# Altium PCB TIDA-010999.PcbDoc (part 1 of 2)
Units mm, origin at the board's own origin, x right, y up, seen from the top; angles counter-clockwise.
Board outline 95 x 90.17 mm, 4 copper layers (Top Layer 1, Top Layer, Bottom Layer, Bottom Layer 1), stack 1.926 mm thick; 90 components, 100 nets, 358 pads, 545 vias.
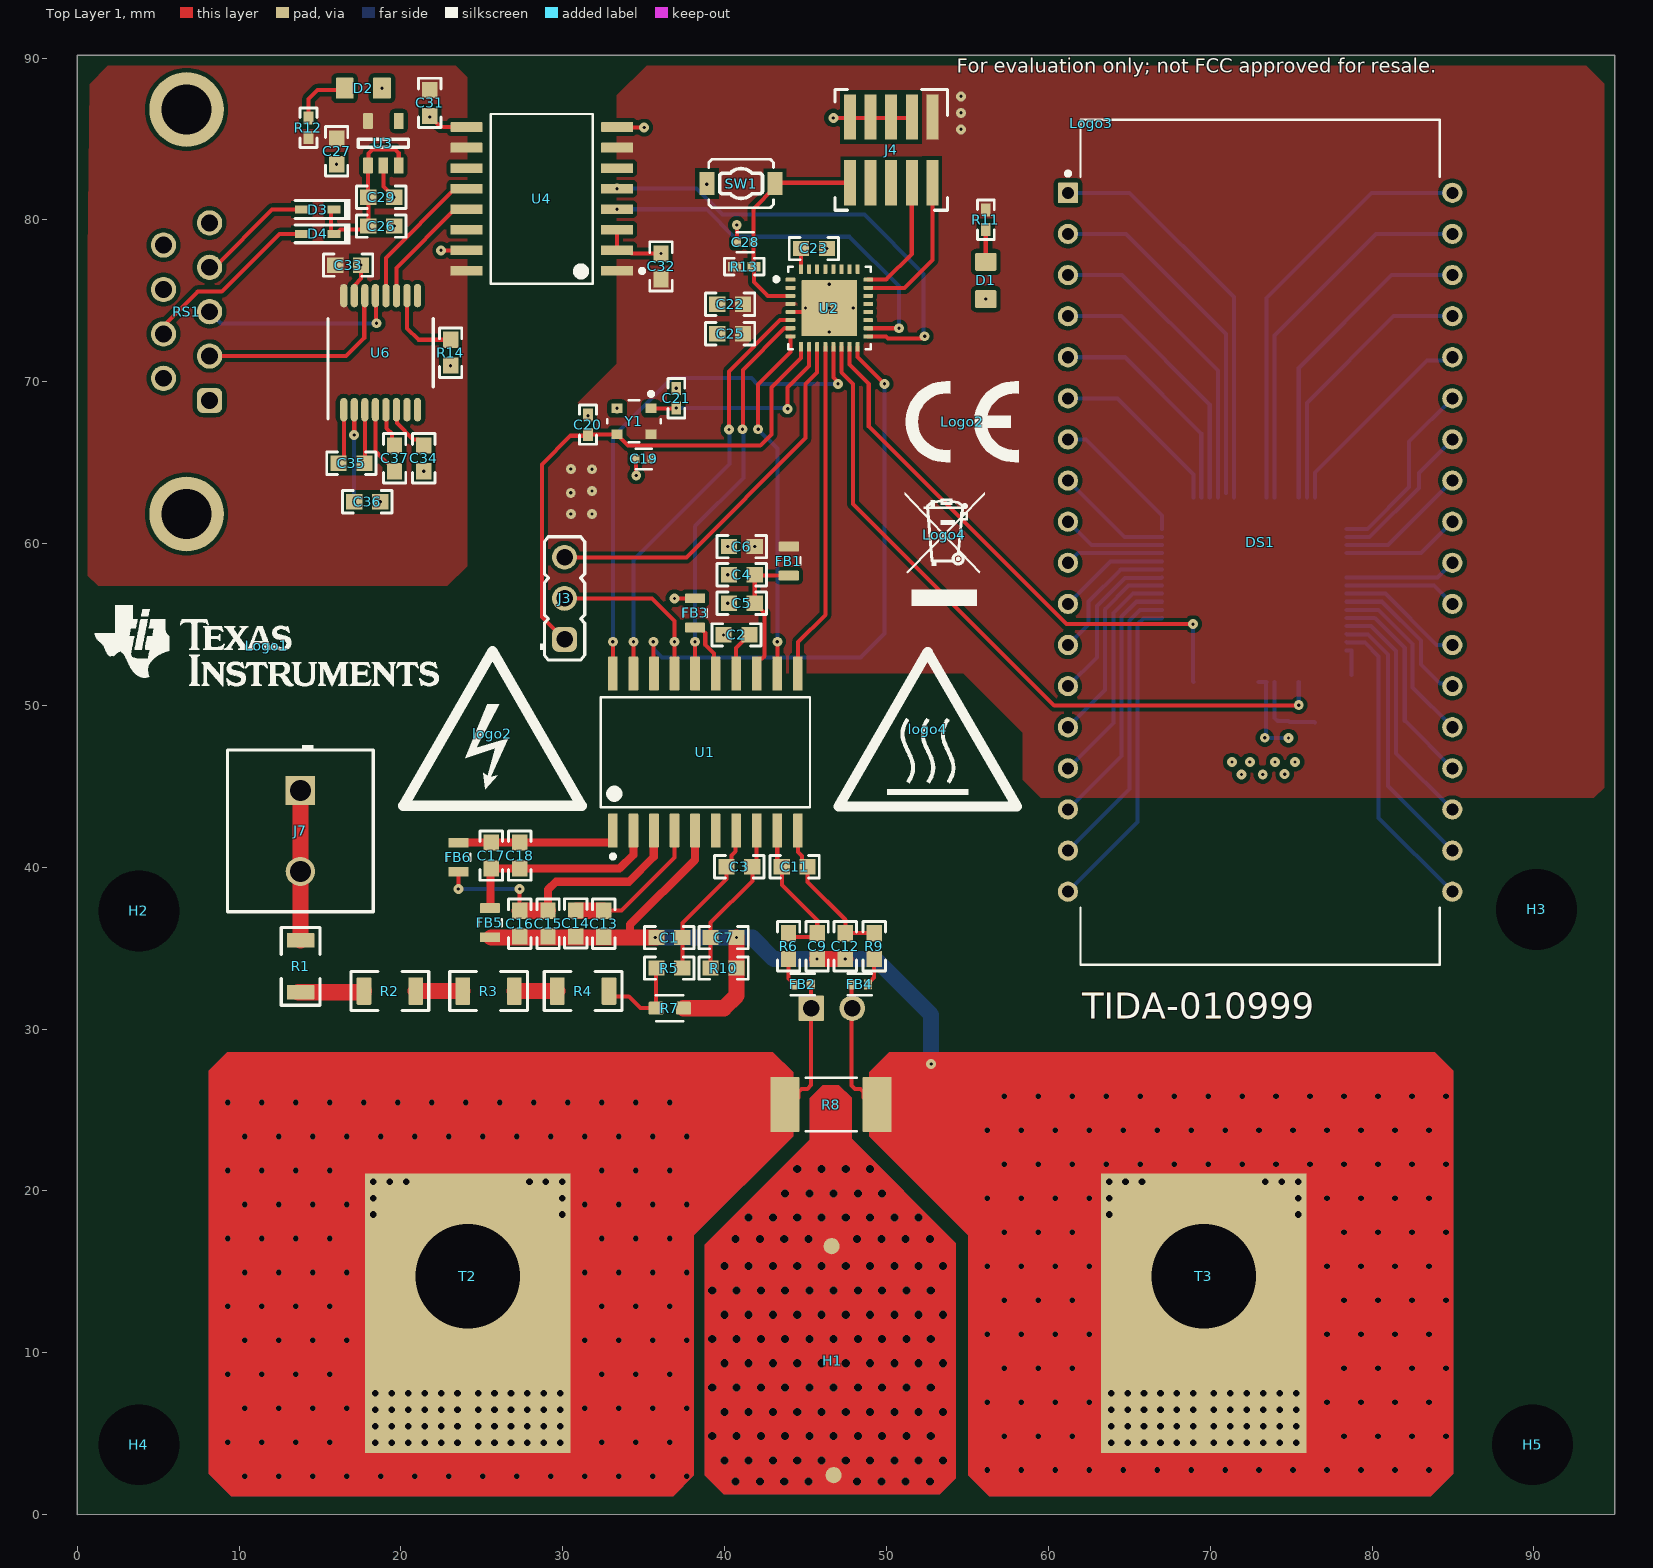
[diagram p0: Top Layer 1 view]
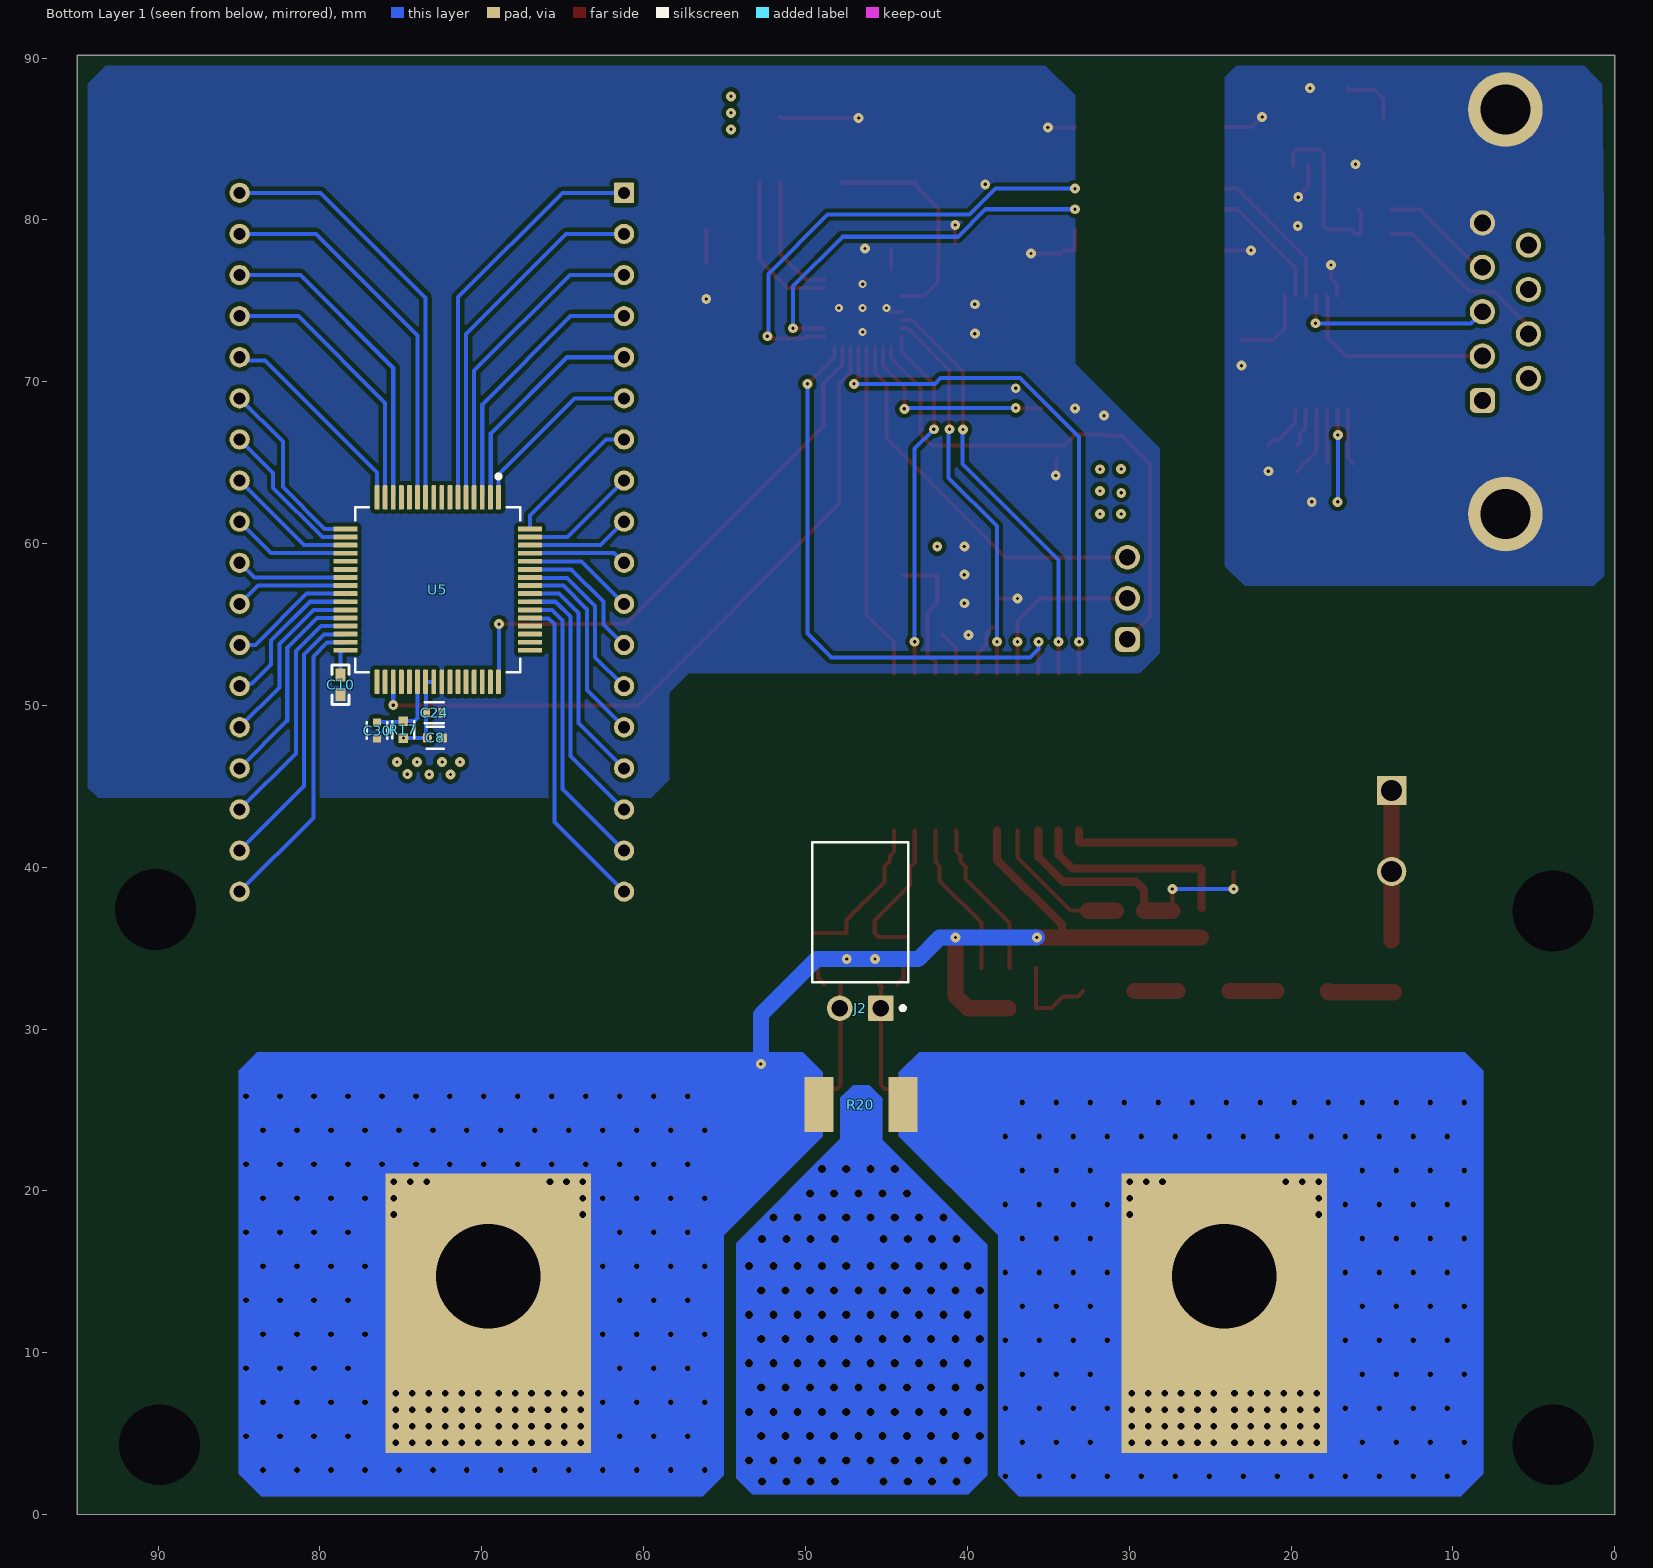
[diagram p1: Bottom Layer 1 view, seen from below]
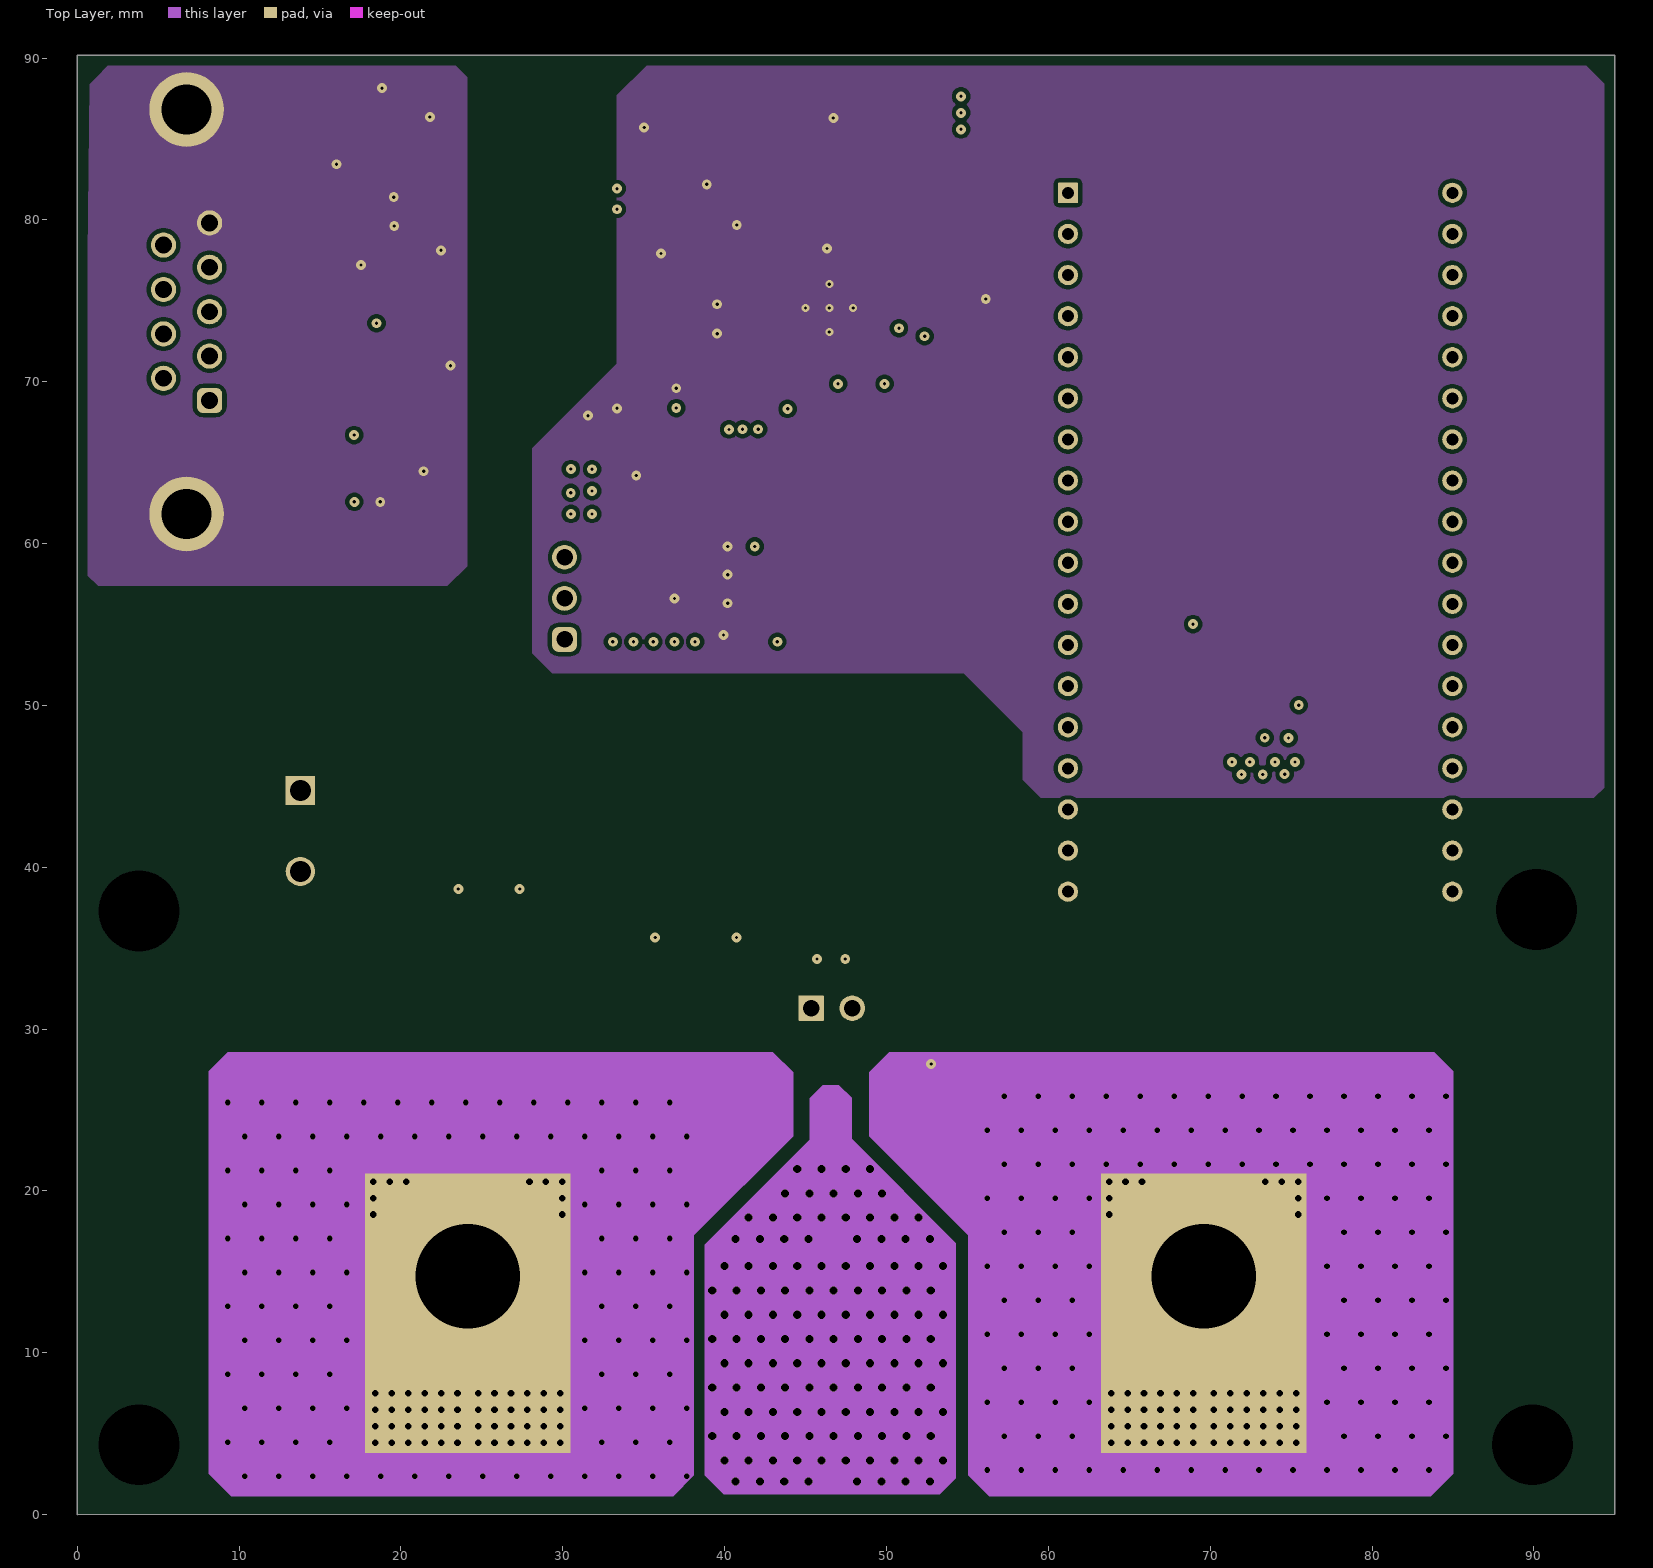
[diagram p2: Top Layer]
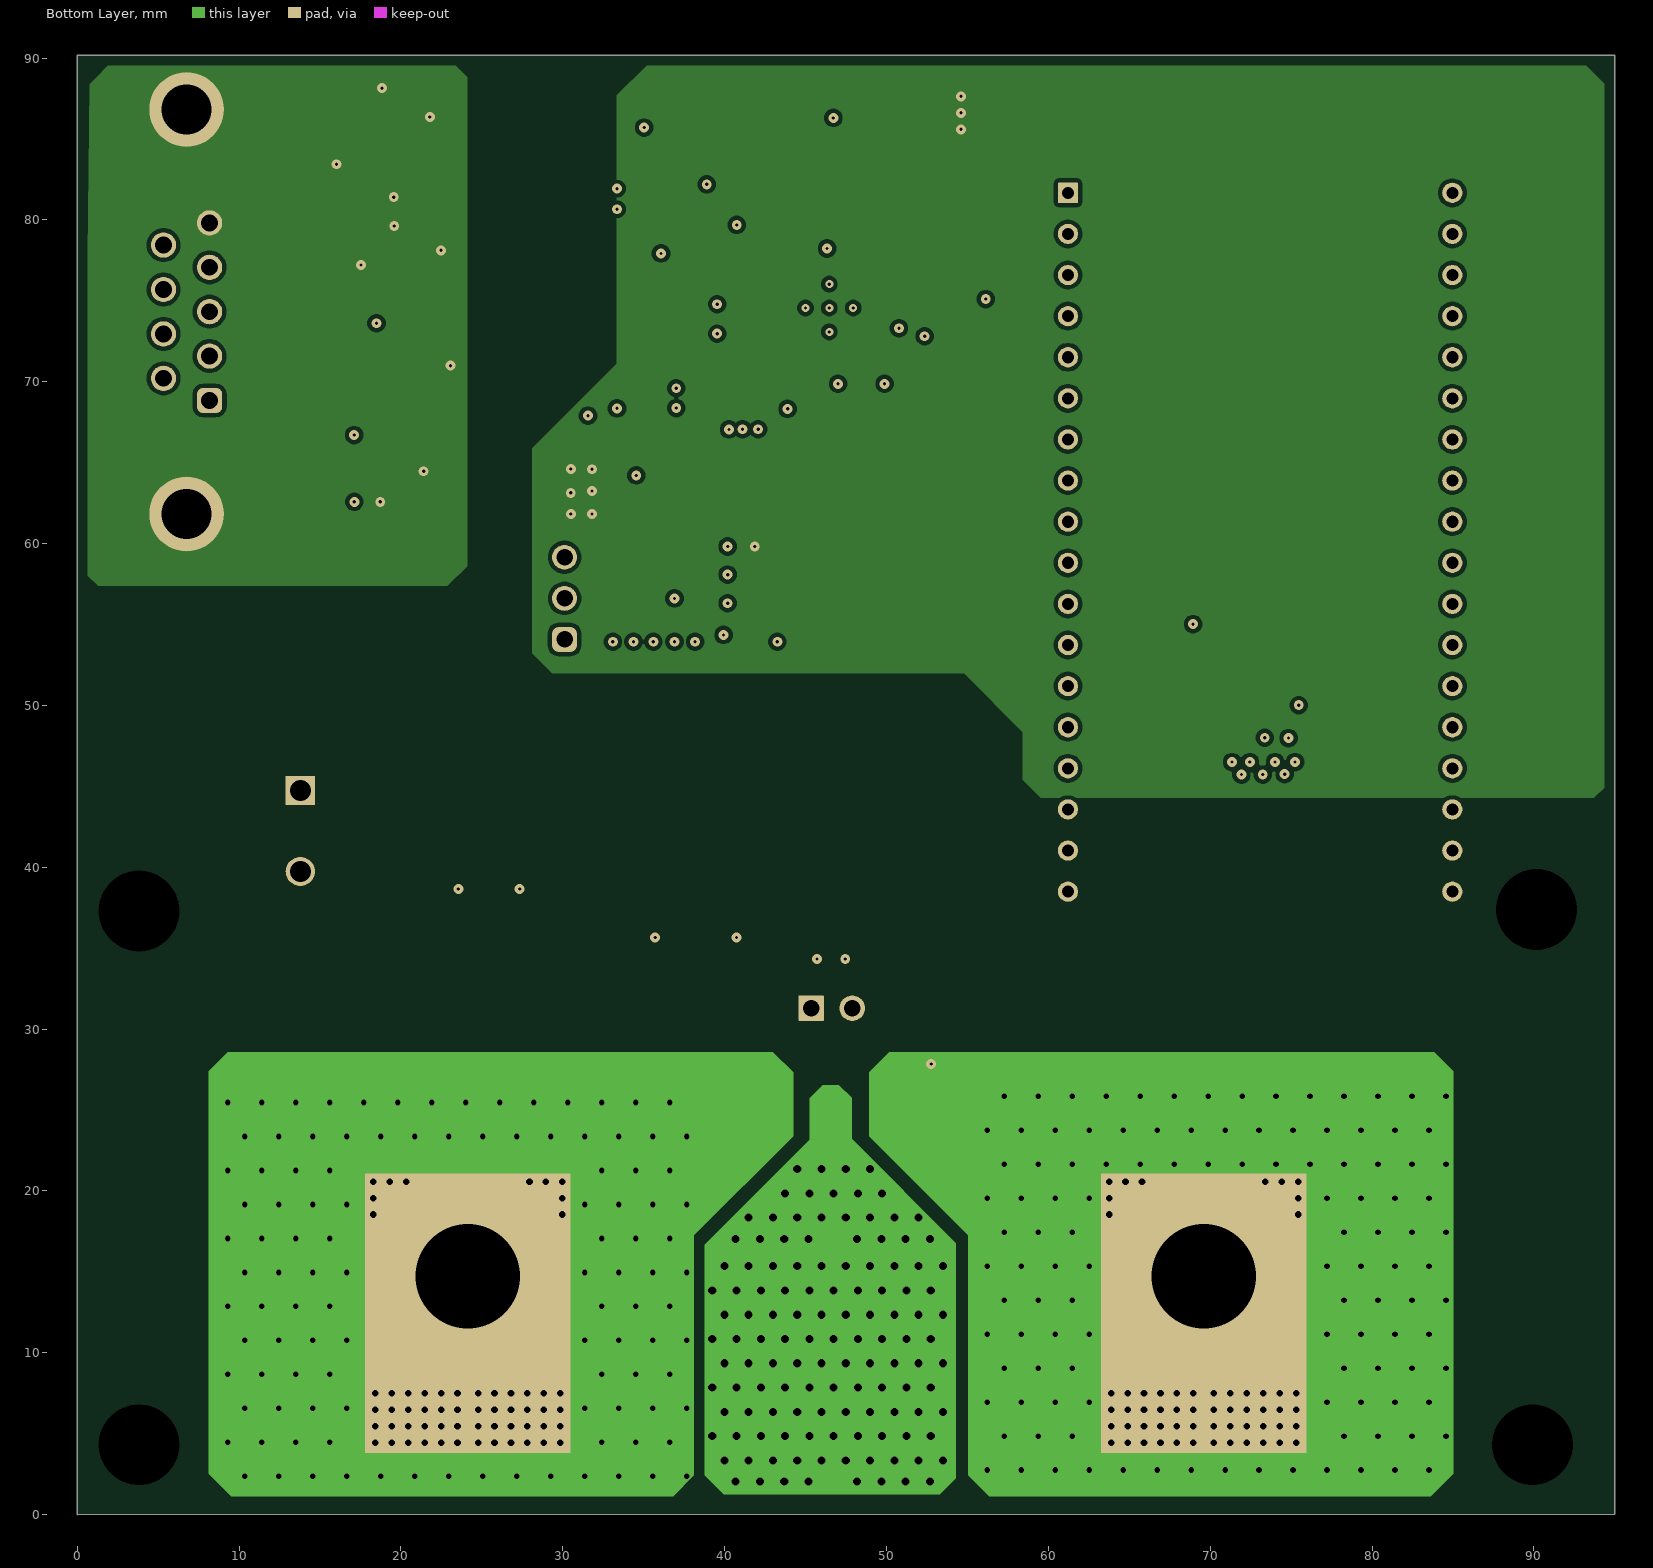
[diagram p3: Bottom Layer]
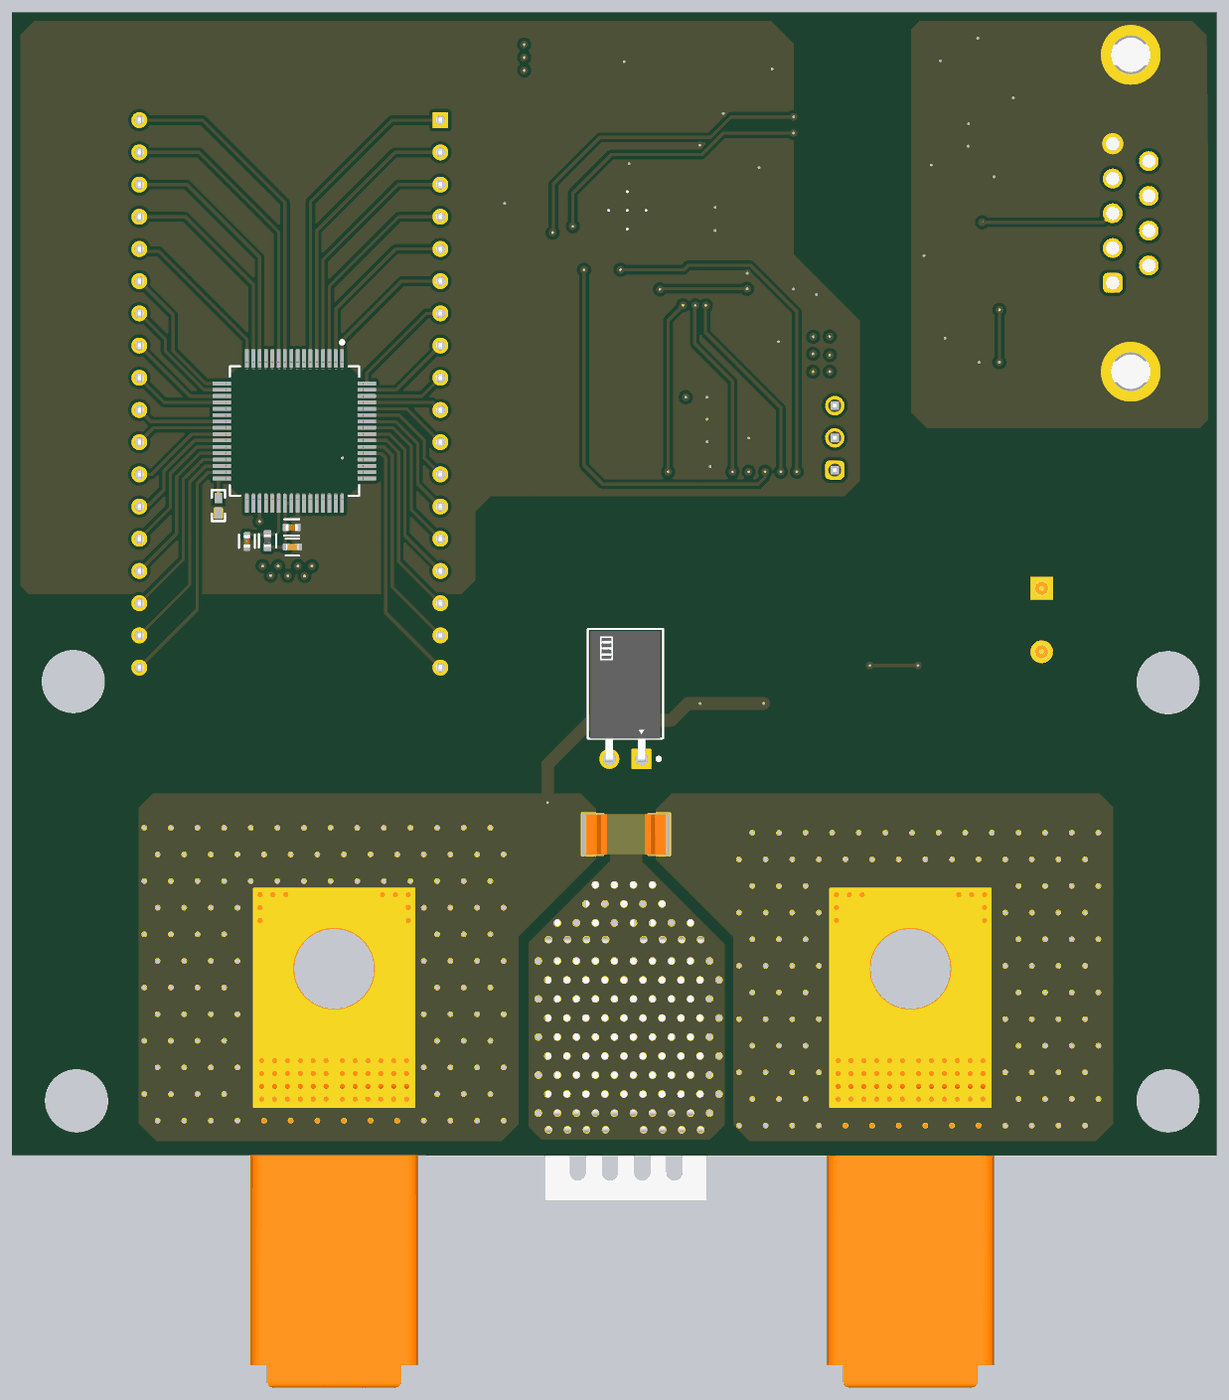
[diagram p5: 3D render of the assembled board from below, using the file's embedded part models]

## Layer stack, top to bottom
Top Solder: solder mask 0.0102, Solder Resist, Dk 3.5
Top Layer 1: signal copper 0.07
Dielectric 1: prepreg 0.0711, PP-006, Dk 4.1
Top Layer: signal copper 0.07
Dielectric1: core 1.5037, FR-4 High Tg, Dk 4.8
Bottom Layer: signal copper 0.07
Dielectric 2: prepreg 0.0711, PP-006, Dk 4.1
Bottom Layer 1: signal copper 0.07
Bottom Solder: solder mask 0.0102, Solder Resist, Dk 3.5

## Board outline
0,0 0,50.797 0,90.164 94.996,90.17 94.996,50.8 94.996,0.03

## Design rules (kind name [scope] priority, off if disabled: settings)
AcuteAngle [All] p1: minimum=4.50000000000000E+0001 checktracksonly=FALSE
AssemblyTestPointUsage [All] p1: valid=2
BoardOutlineClearance BoardOutlineClearance_MountingHoles [OnCopper and InComponentClass('Mounting Holes')] p1: gap=1 ignorepadtopadclearanceinfootprint=FALSE
BoardOutlineClearance BoardOutlineClearance_Poly [OnCopper and IsPoly] p2: gap=0.635 ignorepadtopadclearanceinfootprint=FALSE
BoardOutlineClearance [OnCopper and Not InComponentClass('Logo') and not InComponentClass('FiducialMark') and not InRegion(1000,500,4000,800) and not InPoly] p3: gap=1.016 ignorepadtopadclearanceinfootprint=FALSE
Clearance Clearance_Keepouts [((IsTrack Or IsArc) And Not InPoly) And IsFree and IsKeepOut vs ((IsTrack Or IsArc) And Not InPoly) And IsFree and IsKeepOut] p1: gap=0 ignorepadtopadclearanceinfootprint=FALSE
Clearance Clearance_Poly [InPolygon] p2: gap=0.254 ignorepadtopadclearanceinfootprint=TRUE
Clearance Clearance_FiducialMark [IsKeepOut and InComponentClass('FiducialMark') vs IsPad and InComponentClass('FiducialMark')] p3: gap=0 ignorepadtopadclearanceinfootprint=FALSE
Clearance [All] p4: gap=0.2 ignorepadtopadclearanceinfootprint=TRUE
ComponentClearance ComponentClearance_MountingHoles_FiducialMarks [InComponentClass('Mounting Holes') vs InComponentClass('FiducialMark')] p1: gap=1.27 collisioncheckmode=3 verticalgap=0.254 showdistances=FALSE
ComponentClearance ComponentClearance_Shunt [InComponentClass('Header') vs InComponentClass('Shunt')] p2: gap=0 collisioncheckmode=3 verticalgap=0 showdistances=FALSE
ComponentClearance ComponentClearance_Logo [InComponentClass('Logo')] p3: gap=0.762 collisioncheckmode=3 verticalgap=0.254 showdistances=FALSE
ComponentClearance ComponentClearance_ScrewToNut [(HasFootprint('NY PMS 440 0025 PH')) vs (HasFootprint('Keystone_1902C'))] p4: gap=0.127 collisioncheckmode=3 verticalgap=0.254 showdistances=FALSE
ComponentClearance ComponentClearance_MountingHoles [InComponentClass('Mounting Holes')] p5: gap=2.54 collisioncheckmode=3 verticalgap=2540 showdistances=FALSE
ComponentClearance ComponentClearance_SmallPassives [HasFootprint('0201*') or HasFootprint('0402*') or HasFootprint('0508') or HasFootprint('0603*') or HasFootprint('0612') or HasFootprint('0805*') or HasFootprint('0815*') or HasFootprint('0830*') or HasFootprint('1206*') or HasFootprint('1210*') or HasFootprint('1808*') or HasFootprint('1812*') or HasFootprint('1825*') or HasFootprint('2010*') or HasFootprint('2220*') or HasFootprint('2225*') or HasFootprint('2512*') or HasFootprint('2728*') or HasFootprint('3518*') vs HasFootprint('0201*') or HasFootprint('0402*') or HasFootprint('0508') or HasFootprint('0603*') or HasFootprint('0612') or HasFootprint('0805*') or HasFootprint('0815*') or HasFootprint('0830*') or HasFootprint('1206*') or HasFootprint('1210*') or HasFootprint('1808*') or HasFootprint('1812*') or HasFootprint('1825*') or HasFootprint('2010*') or HasFootprint('2220*') or HasFootprint('2225*') or HasFootprint('2512*') or HasFootprint('2728*') or HasFootprint('3518*')] p6: gap=0.38 collisioncheckmode=3 verticalgap=0.254 showdistances=FALSE
ComponentClearance ComponentClearance_THtoSMT [IsThruComponent vs IsSMTComponent] p7: gap=0.762 collisioncheckmode=3 verticalgap=0.762 showdistances=FALSE
ComponentClearance ComponentClearance_THtoTH [IsThruComponent vs IsThruComponent] p8: gap=0.508 collisioncheckmode=3 verticalgap=0.762 showdistances=FALSE
ComponentClearance [All] p9: gap=0.508 collisioncheckmode=3 verticalgap=0.254 showdistances=FALSE
DiffPairsRouting [All] p1: maxlimit=2.54 minlimit=0.254 mostfreqgap=0.254 toplayer_minwidth=0.381 toplayer_maxwidth=0.381 toplayer_prefwidth=0.381 midlayer1_minwidth=0.381 midlayer1_maxwidth=0.381 midlayer1_prefwidth=0.381 midlayer2_minwidth=0.381 midlayer2_maxwidth=0.381 midlayer2_prefwidth=0.381 bottomlayer_minwidth=0.381 bottomlayer_maxwidth=0.381 bottomlayer_prefwidth=0.381 maxuncoupledlength=25.4
FabricationTestPointUsage TestPointUsage [All] p1: valid=2 allowmultiple=FALSE
FabricationTestpoint Testpoint [All] p1: side=3 testpointundercomponent=TRUE minsize=1.016 maxsize=2.54 preferedsize=1.524 minholesize=0 maxholesize=1.016 preferedholesize=0.813 testpointgrid=0.025 allowsidetop=TRUE allowsidebottom=TRUE usegrid=TRUE gridtolerance=0
FanoutControl Fanout_LCC [IsLCC] p1: bgadir=Out bgaviamode=Centered fanoutstyle=Auto fanoutdirection=Alternating viagrid=0.025 // Fanout_LCC (Default Rule)
FanoutControl Fanout_BGA [IsBGA] p2: bgadir=Out bgaviamode=Centered fanoutstyle=Auto fanoutdirection=Alternating viagrid=0.025 // Fanout_BGA (Default Rule)
FanoutControl Fanout_Default [All] p4: bgadir=Out bgaviamode=Centered fanoutstyle=Auto fanoutdirection=Alternating viagrid=0.025 // Fanout_Default (Default Rule)
FanoutControl Fanout_Small [(CompPinCount < 5)] p5: bgadir=Out bgaviamode=Centered fanoutstyle=Auto fanoutdirection=OutThenIn viagrid=0.025 // Fanout_Small (Default Rule)
HoleSize [All] p1: absolutevalues=TRUE maxlimit=6.375 minlimit=0.2 maxpercent=80.000 minpercent=20.000
MinimumAnnularRing MinimumAnnularRing_ThermalPadVias [IsVia and InAnyComponent] p1: minimumring=0.15
MinimumAnnularRing [All] p2: minimumring=0.2
MinimumSolderMaskSliver MinimumSolderMaskSliver_Logo [InComponentClass('Logo') vs InComponentClass('Logo')] p1: minsoldermaskwidth=0.018
MinimumSolderMaskSliver [All] p2: minsoldermaskwidth=0.1
PlaneConnect [All] p1: planeconnectstyle=Direct reliefexpansion=0.254 reliefentries=4 reliefconductorwidth=0.254 reliefairgap=0.254
PolygonConnect [All] p1: connectstyle=Direct reliefconductorwidth=0.254 reliefentries=4 polygonreliefangle="90 Angle" airgapwidth=0.254
RoutingLayers [All] p1: top layer_v5=TRUE mid layer 1_v5=FALSE mid layer 2_v5=FALSE bottom layer_v5=TRUE
RoutingVias ThermalPadVias [IsVia and InAnyComponent] p1: holewidth=0.2 width=0.5 viastyle="Through Hole" minholewidth=0.2 minwidth=0.5 maxholewidth=0.33 maxwidth=0.6
RoutingVias [All] p2: holewidth=0.406 width=0.864 viastyle="Through Hole" minholewidth=0.2 minwidth=0.61 maxholewidth=1.016 maxwidth=1.651
SilkToBoardRegionClearance [Not ((IsComment or IsDesignator) And (Hide <> 'False')) and not InRegion(1000,500,4000,800)] p1:
SilkToSilkClearance SilkToSilkClearance_Pb-FreeLogo [(HasFootprint('Pb-Free_Overlay_Medium') OR HasFootprint('Pb-Free_Overlay_Small')) vs (HasFootprint('Pb-Free_Overlay_Medium') OR HasFootprint('Pb-Free_Overlay_Small'))] p1: silktosilkclearance=0
SilkToSilkClearance [All] p2: silktosilkclearance=0.1
SilkToSolderMaskClearance SilkToComponentPadClearance [(IsPad or IsFill or IsRegion) and InAnycomponent] p1: minsilkscreentomaskgap=0.127 clearancetoexposedcopper=TRUE
SilkToSolderMaskClearance "Silk to Solder Mask Opening" [All] p2: minsilkscreentomaskgap=0.1 clearancetoexposedcopper=FALSE
SolderMaskExpansion [All] p1: expansion=0.05 istentingtop=FALSE
SupplyNets "Schematic Supply Nets_5" [InNet('HFXIN')] p1: voltage=0.000
SupplyNets "Schematic Supply Nets_40" [InNet('ADC_CLK_IN')] p2: voltage=0.000
SupplyNets "Schematic Supply Nets_39" [InNet('TPS709_IN')] p3: voltage=0.000
SupplyNets "Schematic Supply Nets_38" [InNet('ADC_DOUT_MSP_DIN')] p4: voltage=0.000
SupplyNets "Schematic Supply Nets_37" [InNet('VCC_ISO_RS')] p5: voltage=0.000
SupplyNets "Schematic Supply Nets_36" [InNet('ADC_D\R\D\Y\')] p6: voltage=0.000
SupplyNets "Schematic Supply Nets_35" [InNet('Meter_RX_PC_TX')] p7: voltage=0.000
SupplyNets "Schematic Supply Nets_34" [InNet('RS232_PORT_RTS')] p8: voltage=0.000
SupplyNets "Schematic Supply Nets_33" [InNet('Serial_TX')] p9: voltage=0.000
SupplyNets "Schematic Supply Nets_32" [InNet('UART_TX')] p10: voltage=0.000
SupplyNets "Schematic Supply Nets_31" [InNet('Meter_TX_PC_RX')] p11: voltage=0.000
SupplyNets "Schematic Supply Nets_30" [InNet('Serial_RX_ISO')] p12: voltage=0.000
SupplyNets "Schematic Supply Nets_29" [InNet('Serial_TX_ISO')] p13: voltage=0.000
SupplyNets "Schematic Supply Nets_28" [InNet('SPI_CLK')] p14: voltage=0.000
SupplyNets "Schematic Supply Nets_27" [InNet('GND_ISO_RS')] p15: voltage=0.000
SupplyNets "Schematic Supply Nets_26" [InNet('ADC_C\S\')] p16: voltage=0.000
SupplyNets "Schematic Supply Nets_25" [InNet('VCC')] p17: voltage=0.000
SupplyNets "Schematic Supply Nets_24" [InNet('ADC_DIN_MSP_DOUT')] p18: voltage=0.000
SupplyNets "Schematic Supply Nets_23" [InNet('nRST')] p19: voltage=0.000
SupplyNets "Schematic Supply Nets_22" [InNet('GND')] p20: voltage=0.000
SupplyNets "Schematic Supply Nets_21" [InNet('RS232_PORT_DTR')] p21: voltage=0.000
SupplyNets "Schematic Supply Nets_20" [InNet('HFXOUT')] p22: voltage=0.000
SupplyNets "Schematic Supply Nets_19" [InNet('M0_CLKOUT')] p23: voltage=0.000
SupplyNets "Schematic Supply Nets_18" [InNet('ADC_SYNC_RESET')] p24: voltage=0.000
SupplyNets "Schematic Supply Nets_17" [InNet('Serial_RX')] p25: voltage=0.000
SupplyNets "Schematic Supply Nets_14" [InNet('UART_RX')] p26: voltage=0.000
SupplyNets "Schematic Supply Nets_13" [InNet('HEAT')] p27: voltage=0.000
SupplyNets "Schematic Supply Nets_15" [InNet('VDD_3V3')] p28: voltage=0.000
SupplyNets "Schematic Supply Nets_11" [InNet('I_N')] p29: voltage=0.000
SupplyNets "Schematic Supply Nets_10" [InNet('H_GND')] p30: voltage=0.000
SupplyNets "Schematic Supply Nets_9" [InNet('DCDC_OUT')] p31: voltage=0.000
SupplyNets "Schematic Supply Nets_6" [InNet('HLDO_OUT')] p32: voltage=0.000
SupplyNets "Schematic Supply Nets_4" [InNet('I_P')] p33: voltage=0.000
SupplyNets "Schematic Supply Nets_3" [InNet('DCDC_HGND')] p34: voltage=0.000
SupplyNets "Schematic Supply Nets_2" [InNet('V_DIV-')] p35: voltage=0.000
SupplyNets "Schematic Supply Nets_1" [InNet('HLDO_IN')] p36: voltage=0.000
SupplyNets "Schematic Supply Nets" [InNet('V_DIV+')] p37: voltage=0.000
UnRoutedNet [All] p1: checkbadconnections=TRUE
Width [All] p1: maxlimit=2.54 minlimit=0.152 preferedwidth=0.254 checkconnectedcopper=TRUE
13 further rules are at their usual default settings.

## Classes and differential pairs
component class Header: J3
component class "LCD interface": C8 C10 C24 C30 DS1 R17 U5
component class TIDA-010999-inputs: C1 C2 C3 C4 C5 C6 C7 C9 C11 C12 C13 C14 C15 C16 C17 C18 FB1 FB2 FB3 FB4 FB5 FB6 H1 J2 J7 R1 R2 R3 R4 R5 R6 R7 R8 R9 R10 R20 T2 T3 U1
component class Sheet2: C19 C20 C21 C22 C23 C25 C26 C27 C28 C29 C31 C32 C33 C34 C35 C36 C37 D1 D2 D3 D4 J3 J4 R11 R12 R13 R14 RS1 SH-J1 SW1 U2 U3 U4 U6 Y1
component class Logo: Logo1
component class TIDA-010999_Hardware: H2 H3 H4 H5 Logo1 Logo2 Logo3 Logo4

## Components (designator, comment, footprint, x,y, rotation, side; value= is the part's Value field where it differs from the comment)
C1 "885012006057" 0603 36.582,35.657 r180 top value=100pF
C2 "C1608X7R1H104K080AA" 0603 40.732,54.356 r180 top value=0.1uF
C3 "C0603C472J1GAC7867" 0603 40.907,40.038 r0 top value=4700pF
C4 "C0603C102K5RACTU" 0603 41.059,58.082 r180 top value=1000pF
C5 "C0603C105K3RACTU" 0603 41.059,56.31 r0 top value=1uF
C6 "C0603C105K3RACTU" 0603 41.059,59.817 r0 top value=1uF
C7 "885012006057" 0603 39.932,35.657 r180 top value=100pF
C8 "GMC04X7R105K10NT" FP-GMC04X7R105K10NT_0402-MFG 72.89,48 r0 bottom value=1µF
C9 "885012006057" 0603 45.71,35.124 r270 top value=100pF
C10 "GRM155R61C474KE01" 0402 78.727,51.272 r90 bottom value=0.47uF
C11 "C0603C472J1GAC7867" 0603 44.324,40.034 r0 top value=4700pF
C12 "885012006057" 0603 47.449,35.124 r90 top value=100pF
C13 "C0603C102K5RACTU" 0603 32.534,36.509 r270 top value=1000pF
C14 "C1608X7R1H104K080AA" 0603 30.805,36.527 r270 top value=0.1uF
C15 "C1608X7R1H104K080AA" 0603 29.085,36.512 r270 top value=0.1uF
C16 "C0603C102K5RACTU" 0603 27.335,36.512 r270 top value=1000pF
C17 "C0603C102K5RACTU" 0603 25.573,40.719 r270 top value=1000pF
C18 "C0603C105K3RACTU" 0603 27.335,40.719 r90 top value=1uF
C19 "885012205018" FP-885012205018_0402-MFG 34.99,65.226 r0 top value=100nF
C20 "GRM1555C1H150JA01D" 0402 31.554,67.353 r90 top value=15pF
C21 "GRM1555C1H150JA01D" 0402 37.013,68.972 r270 top value=15pF
C22 "CGA3E2X8R1E104K080AA" 0603 40.338,74.791 r0 top value=0.1uF
C23 "GRM188R61A474KA61D" 0603 45.518,78.232 r180 top value=0.47uF
C24 "GCM155D70E106ME36D" FP-GCM155D70E106ME36D_0402-MFG 72.94,49.545 r0 bottom value=10µF
C25 "GRM188R61A106KAALD" 0603 40.338,72.969 r0 top value=10uF
C26 "GRT188R61H225KE13D" 0603 18.781,79.621 r0 top value=2.2uF
C27 "GRT188R61H225KE13D" 0603 16.022,84.236 r270 top value=2.2uF
C28 "885012205050" FP-885012205050_0402-MFG 41.27,78.613 r0 top value=10nF
C29 "CGA3E1X7R1E105M080AC" 0603 18.781,81.405 r0 top value=1uF
C30 "885012205050" FP-885012205050_0402-MFG 76.473,48.448 r90 bottom value=10nF
C31 "C0603X104K3RACTU" 0603 21.784,87.228 r270 top value=0.1uF
C32 "C0603X104K3RACTU" 0603 36.068,77.127 r90 top value=0.1uF
C33 "CGA3E2X8R1E104K080AA" 0603 16.736,77.206 r180 top value=0.1uF
C34 "CGA3E2X8R1E104K080AA" 0603 21.403,65.266 r90 top value=0.1uF
C35 "CGA3E2X8R1E104K080AA" 0603 16.938,64.958 r180 top value=0.1uF
C36 "CGA3E2X8R1E104K080AA" 0603 17.918,62.576 r180 top value=0.1uF
C37 "CGA3E2X8R1E104K080AA" 0603 19.603,65.266 r270 top value=0.1uF
D1 "CMD17-21SRC/TR8" CMD17-21_Red 56.134,76.255 r270 top value=Red
D2 "CMD17-21SRC/TR8" CMD17-21_Red 17.672,88.138 r0 top value=Red
D3 "1N4148WT" Fairchild_SOD-523F 14.861,80.641 r180 top value=75V
D4 "1N4148WT" Fairchild_SOD-523F 14.861,79.139 r180 top value=75V
DS1 "VIM-878-DP-RC-S-LV" FP-VIM-878-DP-RC-S-LV_PTH_DS_52MM0_22MM0-MFG 73.088,60.082 r270 top
FB1 "BLM21HE472SH1L" FP-BLM21HE472SH1L_0805-MFG 43.962,58.921 r90 top
FB2 "74269244182" FP-74269244182_0402-MFG 44.82,32.755 r0 top
FB3 "BLM21HE472SH1L" FP-BLM21HE472SH1L_0805-MFG 38.172,55.712 r90 top
FB4 "74269244182" FP-74269244182_0402-MFG 48.345,32.757 r180 top
FB5 "BLM21HE472SH1L" FP-BLM21HE472SH1L_0805-MFG 25.495,36.577 r270 top
FB6 "BLM21HE472SH1L" FP-BLM21HE472SH1L_0805-MFG 23.547,40.615 r270 top
H1 "573300D00010G" HEATSINK_573300D00010G 46.559,9.536 r90 top
H2 "5MM HOLE" 5MM_HOLE 3.81,37.3 r0 top
H3 "5MM HOLE" 5MM_HOLE 90.17,37.391 r0 top
H4 "5MM HOLE" 5MM_HOLE 3.81,4.318 r0 top
H5 "5MM HOLE" 5MM_HOLE 89.916,4.318 r0 top
J2 "PPTC021LGBN-RC" FP-PPTC021LGBN-RC_CONN_HDR2-MFG 46.615,37.141 r0 bottom
J3 "22284030" Molex_0022284030 30.105,56.612 r90 top
J4 "FTSH-105-01-L-DV-K" Samtec_FTSH-105-01-x-DV-K 50.292,84.328 r270 top
J7 "1935776" Phoenix_1935776 13.781,42.243 r270 top
Logo1 "Texas Instruments" TI_Stacked_Overlay_Small 11.714,53.69 r0 top
logo2 "DANGER HIGH VOLTAGE" IEC_HighVoltage_Medium 25.654,48.26 r0 top (schematic designator logo1)
Logo2 "CE Mark" CE_Mark_5mm 54.685,67.526 r0 top
Logo3 "FCC disclaimer" FCC_disclaimer 62.661,85.956 r0 top
logo4 "CAUTION HOT SURFACE" IEC_HotSurface_Medium 52.546,48.516 r0 top (schematic designator logo3)
Logo4 "WEEE logo" WEEE_Minimum 53.561,60.533 r0 top
R1 "TNPV12062M00BEEN" TNPV1206 13.799,33.88 r270 top value=2.00Meg
R2 "TNPV12062M00BEEN" TNPV1206 19.315,32.351 r0 top value=2.00Meg
R3 "TNPV12062M00BEEN" TNPV1206 25.411,32.351 r0 top value=2.00Meg
R4 "TNPV12062M00BEEN" TNPV1206 31.253,32.351 r0 top value=2.00Meg
R5 "CRCW060349R9FKEA" 0603 36.582,33.771 r0 top value=49.9
R6 "CRCW060349R9FKEA" 0603 43.948,35.124 r90 top value=49.9
R7 "8k" FP-RT0603BRE078KL_0603-MFG 36.607,31.289 r180 top
R8 "EBWM2512F1L00S9" FP-EBWM2512F1L00S9_2512-MFG 46.574,25.34 r180 top value=1m
R9 "CRCW060349R9FKEA" 0603 49.239,35.124 r90 top value=49.9
R10 "CRCW060349R9FKEA" 0603 39.932,33.771 r180 top value=49.9
R11 "RC0402FR-07470RL" 0402 56.134,80.01 r90 top value=470
R12 "RC0402FR-07470RL" 0402 14.281,85.69 r270 top value=470
R13 "CRCW040247K0JNED" 0402 41.207,77.105 r180 top value=47k
R14 "CRCW06034K70JNEA" 0603 23.065,71.795 r90 top value=4.7k
R17 "47K" FP-RCC040247K0FKED_0402-MFG 74.851,48.498 r270 bottom value=47k
R20 "WSLF2512L5000FEA" WSLF2512L5000 46.574,25.34 r180 bottom value=0.0005
RS1 "2-5747706-0" TE_2-5747706-0 6.752,74.327 r270 top
SW1 "TL1015AF160QG" SW_TL1015AF160QG 41.013,82.247 r0 top
T2 "CB70-14-CY" CB70-14-CY 24.13,14.732 r90 top
T3 "CB70-14-CY" CB70-14-CY 69.596,14.732 r90 top
U1 "AMC131M03DFM" DFM0020A-MFG 38.807,47.117 r90 top
U2 "MSPM0G1506SRHB" RHB0032N-MFG 46.468,74.555 r0 top
U3 "TPS70933DBVR" DBV0005A_N 18.912,84.736 r90 top
U4 "ISO6731DWR" DW0016A-MFG 28.702,81.293 r180 top
U5 "MSPM0L2227QPMQ1" PM0064A-MFG 72.723,57.155 r270 bottom
U6 "TRS3232EIDBR" DB0016A_L 18.744,71.795 r90 top
Y1 "CDC6CE008192ADLE" DLE0004A-MFG 34.4,67.553 r270 top

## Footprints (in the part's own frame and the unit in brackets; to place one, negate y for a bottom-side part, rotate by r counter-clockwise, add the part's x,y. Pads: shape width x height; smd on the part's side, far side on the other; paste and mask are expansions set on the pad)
5MM_HOLE [mm]
  round 4.7 hole 5 unplated mask+0.102: ""(0,0)
0402 [mm] "0402 from SM-752 data"
  rect 0.8x0.6 smd: 1(-0.6,0) 2(0.6,0)
  silkscreen extent -1.22,-0.52 1.22,0.52, body extent -0.55,-0.3 0.55,0.3, height 0.6
0603 [mm] "0603 from SM-752 data"
  rect 1x0.95 smd: 1(-0.8,0) 2(0.8,0)
  silkscreen extent -1.52,-0.69 1.52,0.69, body extent -0.87,-0.47 0.87,0.47, height 1
CB70-14-CY [mil] "Terminal 90A Lug"
  rect 680x500 hole 254 copper offset -90,0 paste-99999: 1(0,0)
  body extent -1300,-260 250,260, height 714
CE_Mark_5mm [mm] "Minimum text height for CE Mark"
  silkscreen extent -3.5,-2.5 3.5,2.5
CMD17-21_Red [mm] "SMD, 2-Leads, Body 2x1.25mm"
  rrect9% 1.1x1.3 smd: 1(-1.15,0) 2(1.15,0)
  body extent -1,-0.62 1,0.62, height 1.09
DB0016A_L [mm] "SOP, 16-Leads, Body 6.2x5.3mm, Pitch 0.65mm, IPC High Density"
  oval 1.45x0.45 smd: 1(-3.525,2.275) 2(-3.525,1.625) 3(-3.525,0.975) 4(-3.525,0.325) 5(-3.525,-0.325) 6(-3.525,-0.975) 7(-3.525,-1.625) 8(-3.525,-2.275) 9(3.525,-2.275) 10(3.525,-1.625) 11(3.525,-0.975) 12(3.525,-0.325) 13(3.525,0.325) 14(3.525,0.975) 15(3.525,1.625) 16(3.525,2.275)
  silkscreen extent -4.1,-3.25 2.1,3.25, body extent -3.91,-3.1 3.91,3.1, height 2
DBV0005A_N [mm] "SOT23, 5-Leads, Body 2.9x1.6mm, Pitch 0.95mm, Lead Span 2.8mm, IPC Medium Density"
  rrect17% 1x0.6 smd: 1(-1.375,0.95) 2(-1.375,0) 3(-1.375,-0.95) 4(1.375,-0.95) 5(1.375,0.95)
  silkscreen extent -0.25,-1.55 0.25,1.55, body extent -1.42,-1.46 1.42,1.46, height 1.09
DFM0020A-MFG [mm]
  rrect17% 2.1x0.6 smd paste+0 mask+0: 1(-4.85,5.715) 2(-4.85,4.445) 3(-4.85,3.175) 4(-4.85,1.905) 5(-4.85,0.635) 6(-4.85,-0.635) 7(-4.85,-1.905) 8(-4.85,-3.175) 9(-4.85,-4.445) 10(-4.85,-5.715) 11(4.85,-5.715) 12(4.85,-4.445) 13(4.85,-3.175) 14(4.85,-1.905) 15(4.85,-0.635) 16(4.85,0.635) 17(4.85,1.905) 18(4.85,3.175) 19(4.85,4.445) 20(4.85,5.715)
  silkscreen extent -6.57,-6.47 3.4,6.47, body extent -6,-6.72 6,6.72, height 0.25
DLE0004A-MFG [mm]
  rrect17% 0.6x0.7 smd paste-1000 mask+0: 1(-0.8,1.05) 2(-0.8,-1.05) 3(0.8,-1.05) 4(0.8,1.05)
  silkscreen extent -1.82,-1.65 1.3,1.65, body extent -1.4,-1.75 1.4,1.75, height 0.25
DW0016A-MFG [mm]
  rrect17% 2x0.6 smd paste+0 mask+0: 1(-4.65,4.445) 2(-4.65,3.175) 3(-4.65,1.905) 4(-4.65,0.635) 5(-4.65,-0.635) 6(-4.65,-1.905) 7(-4.65,-3.175) 8(-4.65,-4.445) 9(4.65,-4.445) 10(4.65,-3.175) 11(4.65,-1.905) 12(4.65,-0.635) 13(4.65,0.635) 14(4.65,1.905) 15(4.65,3.175) 16(4.65,4.445)
  silkscreen extent -6.32,-5.25 3.15,5.25, body extent -5.75,-5.35 5.75,5.35, height 0.25
Fairchild_SOD-523F [mm] "SMD, 2-Leads, Body 1.2x0.8mm"
  rect 0.8x0.5 smd: 1(-1,0) 2(1,0)
  silkscreen extent -2.03,-0.65 1.4,0.65, body extent -0.65,-0.45 0.65,0.45, height 0.7
FCC_disclaimer [mm]
FP-74269244182_0402-MFG [mm]
  rrect20% 0.5x0.6 smd paste+0 mask+0: 1(-0.5,0) 2(0.5,0)
  silkscreen extent -0.75,-0.68 0.75,0.67, body extent -0.85,-0.4 0.85,0.4, height 0.25
FP-885012205018_0402-MFG [mm]
  rrect20% 0.5x0.5 smd paste+0 mask+0: 1(-0.5,0) 2(0.5,0)
  silkscreen extent -0.5,-0.62 0.5,0.63, body extent -0.85,-0.37 0.85,0.38, height 0.25
FP-885012205050_0402-MFG [mm]
  rrect20% 0.5x0.5 smd paste+0 mask+0: 1(-0.5,0) 2(0.5,0)
  silkscreen extent -0.52,-0.63 0.53,0.63, body extent -0.85,-0.38 0.85,0.37, height 0.25
FP-BLM21HE472SH1L_0805-MFG [mm]
  rrect17% 0.6x1.25 smd paste+0 mask+0: 1(-0.9,0) 2(0.9,0)
  silkscreen extent -0.23,-0.72 0.23,0.72, body extent -1.3,-0.82 1.3,0.82, height 0.25
FP-EBWM2512F1L00S9_2512-MFG [mm] "Recommended Land Pattern"
  rrect6% 1.8x3.4 smd paste+0 mask+0: 1(-2.85,0) 2(2.85,0)
  silkscreen extent -1.58,-1.65 1.58,1.65, body extent -3.15,-1.5 3.15,1.5, height 1.1
FP-GCM155D70E106ME36D_0402-MFG [mm]
  rrect22% 0.45x0.6 smd paste+0 mask+0: 1(-0.475,0) 2(0.475,0)
  silkscreen extent -0.6,-0.65 0.6,0.65, body extent -0.5,-0.25 0.5,0.25, height 0.7
FP-GMC04X7R105K10NT_0402-MFG [mil]
  rrect19% 21x22 smd paste+0 mask+0: 1(-19,0) 2(19,0)
  silkscreen extent -21,-27 21,27, body extent -20,-10 20,10, height 24
FP-PPTC021LGBN-RC_CONN_HDR2-MFG [mm]
  rrect6% 1.57x1.57 hole 1.02 paste-2539.97 mask+0: 1(-1.27,5.85)
  round 1.57 hole 1.02 paste-2539.97 mask+0: 2(1.27,5.85)
  silkscreen extent -2.97,-4.4 2.97,5.97, body extent -2.79,-4.25 2.79,6.05, height 2.74
FP-RCC040247K0FKED_0402-MFG [mm]
  rrect17% 0.6x0.6 smd paste+0 mask+0: 1(-0.525,0) 2(0.525,0)
  silkscreen extent -0.53,-0.67 0.53,0.67, body extent -0.5,-0.25 0.5,0.25, height 0.4
FP-RT0603BRE078KL_0603-MFG [mm]
  rrect13% 0.9x0.8 smd paste+0 mask+0: 1(-0.85,0) 2(0.85,0)
  silkscreen extent -0.85,-0.81 0.86,0.8, body extent -1.4,-0.55 1.4,0.55, height 0.25
FP-VIM-878-DP-RC-S-LV_PTH_DS_52MM0_22MM0-MFG [mm]
  rrect8% 1.25x1.25 hole 0.75 paste-2539.97 mask+0: 1(-21.59,-11.875)
  round 1.25 hole 0.75 paste-2539.97 mask+0: 2(-19.05,-11.875) 3(-16.51,-11.875) 4(-13.97,-11.875) 5(-11.43,-11.875) 6(-8.89,-11.875) 7(-6.35,-11.875) 8(-3.81,-11.875) 9(-1.27,-11.875) 10(1.27,-11.875) 11(3.81,-11.875) 12(6.35,-11.875) 13(8.89,-11.875) 14(11.43,-11.875) 15(13.97,-11.875) 16(16.51,-11.875) 17(19.05,-11.875) 18(21.59,-11.875) 19(21.59,11.875) 20(19.05,11.875) 21(16.51,11.875) 22(13.97,11.875) 23(11.43,11.875) 24(8.89,11.875) 25(6.35,11.875) 26(3.81,11.875) 27(1.27,11.875) 28(-1.27,11.875) 29(-3.81,11.875) 30(-6.35,11.875) 31(-8.89,11.875) 32(-11.43,11.875) 33(-13.97,11.875) 34(-16.51,11.875) 35(-19.05,11.875) 36(-21.59,11.875)
  silkscreen extent -26.1,-12 26.1,11.1, body extent -27.2,-12.6 26.2,12.6, height 0.25
HEATSINK_573300D00010G [mm] "Aavid"
  round 1 smd: 1(-7.1,-0.175) 2(7.05,-0.05)
  Top Layer 1 region: -6.3,6.85 -7.7,6.85 -7.7,-6.85 -6.3,-6.85
  Top Layer 1 region: 6.3,-6.85 7.7,-6.85 7.7,6.85 6.3,6.85
  body extent -13.08,-6.35 13.08,6.35, height 10.16
IEC_HighVoltage_Medium [mm]
  silkscreen extent -5.51,-4.46 5.51,5.09
IEC_HotSurface_Medium [mm]
  silkscreen extent -5.51,-4.76 5.51,4.78
Molex_0022284030 [mm] "Header, 2.54mm, 3x1, Tin, TH"
  rrect50% 1.53x1.53 hole 1.02: 1(-2.54,0)
  round 1.53 hole 1.02: 2(0,0) 3(2.54,0)
  silkscreen extent -3.81,-1.24 3.81,1.5, body extent -3.81,-1.24 3.81,1.24, height 8.38
Phoenix_1935776 [mm] "Terminal Block, 2x1, 5mm, TH"
  rect 1.8x1.8 hole 1.3: 1(-2.5,0)
  round 1.8 hole 1.3: 2(2.5,0)
  silkscreen extent -5.3,-4.5 5,4.5, body extent -5,-4.5 5,4.5, height 13.5
PM0064A-MFG [mm]
  rrect33% 1.5x0.3 smd paste+0 mask+0: 1(-5.7,3.75) 2(-5.7,3.25) 3(-5.7,2.75) 4(-5.7,2.25) 5(-5.7,1.75) 6(-5.7,1.25) 7(-5.7,0.75) 8(-5.7,0.25) 9(-5.7,-0.25) 10(-5.7,-0.75) 11(-5.7,-1.25) 12(-5.7,-1.75) 13(-5.7,-2.25) 14(-5.7,-2.75) 15(-5.7,-3.25) 16(-5.7,-3.75) 33(5.7,-3.75) 34(5.7,-3.25) 35(5.7,-2.75) 36(5.7,-2.25) 37(5.7,-1.75) 38(5.7,-1.25) 39(5.7,-0.75) 40(5.7,-0.25) 41(5.7,0.25) 42(5.7,0.75) 43(5.7,1.25) 44(5.7,1.75) 45(5.7,2.25) 46(5.7,2.75) 47(5.7,3.25) 48(5.7,3.75)
  rrect33% 0.3x1.5 smd paste+0 mask+0: 17(-3.75,-5.7) 18(-3.25,-5.7) 19(-2.75,-5.7) 20(-2.25,-5.7) 21(-1.75,-5.7) 22(-1.25,-5.7) 23(-0.75,-5.7) 24(-0.25,-5.7) 25(0.25,-5.7) 26(0.75,-5.7) 27(1.25,-5.7) 28(1.75,-5.7) 29(2.25,-5.7) 30(2.75,-5.7) 31(3.25,-5.7) 32(3.75,-5.7) 49(3.75,5.7) 50(3.25,5.7) 51(2.75,5.7) 52(2.25,5.7) 53(1.75,5.7) 54(1.25,5.7) 55(0.75,5.7) 56(0.25,5.7) 57(-0.25,5.7) 58(-0.75,5.7) 59(-1.25,5.7) 60(-1.75,5.7) 61(-2.25,5.7) 62(-2.75,5.7) 63(-3.25,5.7) 64(-3.75,5.7)
  silkscreen extent -7.12,-5.1 5.1,5.1, body extent -6,-6 6,6, height 1.6
RHB0032N-MFG [mm]
  rrect40% 0.6x0.25 smd paste+0 mask+0: 1(-2.4,1.75) 2(-2.4,1.25) 3(-2.4,0.75) 4(-2.4,0.25) 5(-2.4,-0.25) 6(-2.4,-0.75) 7(-2.4,-1.25) 8(-2.4,-1.75) 17(2.4,-1.75) 18(2.4,-1.25) 19(2.4,-0.75) 20(2.4,-0.25) 21(2.4,0.25) 22(2.4,0.75) 23(2.4,1.25) 24(2.4,1.75)
  rrect40% 0.25x0.6 smd paste+0 mask+0: 9(-1.75,-2.4) 10(-1.25,-2.4) 11(-0.75,-2.4) 12(-0.25,-2.4) 13(0.25,-2.4) 14(0.75,-2.4) 15(1.25,-2.4) 16(1.75,-2.4) 25(1.75,2.4) 26(1.25,2.4) 27(0.75,2.4) 28(0.25,2.4) 29(-0.25,2.4) 30(-0.75,2.4) 31(-1.25,2.4) 32(-1.75,2.4)
  rrect3% 3.45x3.45 smd paste-1000 mask+0: 33(0,0)
  silkscreen extent -3.4,-2.55 2.55,2.55, body extent -2.8,-2.8 2.8,2.8, height 0.25
Samtec_FTSH-105-01-x-DV-K [mm] "Header(Shrouded), 1.27mm, 5x2, SMT"
  rect 2.79x0.74 smd: 1(-2.035,2.54) 2(2.035,2.54) 3(-2.035,1.27) 4(2.035,1.27) 5(-2.035,0) 6(2.035,0) 7(-2.035,-1.27) 8(2.035,-1.27) 9(-2.035,-2.54) 10(2.035,-2.54)
  silkscreen extent -3.73,-3.48 3.73,3.48, body extent -2.92,-3.18 2.92,3.17, height 6.13
SW_TL1015AF160QG [mm] "E-Switch"
  rect 0.95x1.4 smd: 1(-2.1,0) 2(2.1,0)
  silkscreen extent -2,-1.5 2,1.5, body extent -2.3,-1.5 2.3,1.5, height 2
TE_2-5747706-0 [mil] "Receptacle, D-SUB-9, 2.74mm, TH"
  rrect50% 61.5x61.5 hole 41: 1(216,56)
  round 61.5 hole 41: 2(108,56) 3(0,56) 4(-108,56) 5(-216,56) 6(162,-56) 7(54,-56) 8(-54,-56) 9(-162,-56)
  round 181.5 hole 121: 10(492,0) 11(-492,0)
  body extent -606,-248 607,248, height 479
TI_Stacked_Overlay_Small [mm]
  silkscreen extent -10.63,-2.49 10.63,2.49
TNPV1206 [mm] "VISHAY"
  rrect11% 0.9x1.7 smd: 1(-1.6,0) 2(1.6,0)
  silkscreen extent -2.4,-1.2 2.4,1.2, body extent -1.67,-0.87 1.67,0.87, height 0.65
WEEE_Minimum [mm] "WEEElie bin"
  silkscreen extent -2.42,-4.38 2.52,2.65
WSLF2512L5000 [mm] "SMD, 2-Leads, Body 6.35x3.02mm"
  rrect6% 1.8x3.4 smd: 1(-2.6,0) 2(2.6,0)
  body extent -3.18,-1.59 3.17,1.59, height 1.22

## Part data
C1 C7 C9 C12: library part CMP-0006822-4, "CAP, CERM, 100 pF, 50 V, +/- 5%, C0G/NP0, 0603", Cap_Case=0603, Manufacturer="Wurth Elektronik", TempCo=C0G/NP0, Tolerance_%=5%, Value1=Unknown, Value2=50V, ValueDisplayed=100pF
C2 C14 C15: library part CMP-0007044-5, "CAP, CERM, 0.1 uF, 50 V, +/- 10%, X7R, 0603", Cap_Case=0603, Manufacturer=TDK, Supplier Part Number 1=445-1314-1-ND, TempCo=X7R, Tolerance_%=10%, Value1="0.0296 ohm", Value2=50V, ValueDisplayed=0.1uF
C3 C11: library part CMP-0006941-4, "CAP, CERM, 4700 pF, 100 V, +/- 5%, C0G/NP0, 0603", Cap_Case=0603, Manufacturer=Kemet, Supplier Part Number 1=399-9974-1-ND, TempCo=C0G/NP0, Tolerance_%=5%, Value1=Unknown, Value2=100V, ValueDisplayed=4700pF
C4 C13 C16 C17: library part CMP-0006847-4, "CAP, CERM, 1000 pF, 50 V, +/- 10%, X7R, 0603", Cap_Case=0603, Manufacturer=Kemet, Supplier Part Number 1=399-1082-1-ND, TempCo=X7R, Tolerance_%=10%, Value1=Unknown, Value2=50V, ValueDisplayed=1000pF
C5 C6 C18: library part CMP-0006867-4, "CAP, CERM, 1 uF, 25 V, +/- 10%, X7R, 0603", Cap_Case=0603, Manufacturer=Kemet, Supplier Part Number 1=399-7376-1-ND, TempCo=X7R, Tolerance_%=10%, Value1=Unknown, Value2=25V, ValueDisplayed=1uF
C8: library part CMP-0093200-1, "1µF ±10% 10V Ceramic Capacitor X7R 0402 (1005 Metric)", Digikey Part Number=2571-GMC04X7R105K10NTTR-ND, Manufacturer="Cal-Chip Electronics", Operating Temperature Range="-55°C to +125°C", TempCo=15%, Temperature Characteristic=X7R, Tolerance_%=10%, ValueDisplayed=1uF
C10: library part CMP-0006600-2, "CAP, CERM, 0.47 uF, 16 V, +/- 10%, X5R, 0402", Cap_Case=0402, Manufacturer=MuRata, TempCo=X5R, Tolerance_%=10%, Value1=Unknown, Value2=16V, ValueDisplayed=0.47uF
C19: library part CMP-0090362-1, "0.1µF ±10% 10V Ceramic Capacitor X7R 0402 (1005 Metric)", Digikey Part Number=732-7513-1-ND, Manufacturer="Wurth Electronics", Mouser Part Number=710-885012205018, Operating Temperature Range="-55°C to +125°C", TempCo=15%, Temperature Characteristic=X7R, Tolerance_%=10%, ValueDisplayed=0.1uF
C20 C21: library part CMP-0006420-2, "CAP, CERM, 15 pF, 50 V, +/- 5%, C0G/NP0, 0402", Cap_Case=0402, Manufacturer=MuRata, Supplier Part Number 1=81-GRM1555C1H150JA1D, TempCo=C0G/NP0, Tolerance_%=5%, Value1=Unknown, Value2=50V, ValueDisplayed=15pF
C22 C33 C34 C35 C36 C37: library part CMP-0007090-4, "CAP, CERM, 0.1 uF, 25 V, +/- 10%, X8R, AEC-Q200 Grade 0, 0603", Cap_Case=0603, Manufacturer=TDK, Supplier Part Number 1=445-5885-1-ND, TempCo=X8R, Tolerance_%=10%, Value1=Unknown, Value2=25V, ValueDisplayed=0.1uF
C23: library part CMP-0007328-5, "CAP, CERM, 0.47 uF, 10 V, +/- 10%, X5R, 0603", Cap_Case=0603, Manufacturer=MuRata, Supplier Part Number 1=490-1539-1-ND, TempCo=X5R, Tolerance_%=10%, Value1=Unknown, Value2=10V, ValueDisplayed=0.47uF
C24: library part CMP-0122740-4, "10 uF ±20% 2.5V Ceramic Capacitor X7T 0402 (1005 Metric)", Manufacturer=Murata, Operating Temperature Range="-55°C to +125°C", TempCo=+22/-33%, Temperature Characteristic=X7T, Tolerance_%=20%, ValueDisplayed=10uF
C25: library part CMP-0086193-1, "CAP, CERM, 10 µF, 10 V,+/- 10%, X5R, 0603", Cap_Case=0603, Manufacturer=MuRata, TempCo=X5R, Tolerance_%=10%, Value2=10V, ValueDisplayed=10µF
C26 C27: library part CMP-0007502-5, "CAP, CERM, 2.2 uF, 50 V, +/- 10%, X5R, AEC-Q200 Grade 3, 0603", Cap_Case=0603, Manufacturer=MuRata, Supplier Part Number 1=490-12332-1-ND, TempCo=X5R, Tolerance_%=10%, Value1=Unknown, Value2=50V, ValueDisplayed=2.2uF
C28 C30: library part CMP-0090363-1, "10000pF ±10% 25V Ceramic Capacitor X7R 0402 (1005 Metric)", Digikey Part Number=732-7545-1-ND, Manufacturer="Wurth Electronics", Mouser Part Number=710-885012205050, Operating Temperature Range="-55°C to +125°C", TempCo=15%, Temperature Characteristic=X7R, Tolerance_%=10%, ValueDisplayed=10nF
C29: library part CMP-0082113-1, "CAP, CERM, 1 µF, 25 V,+/- 20%, X7R, AEC-Q200 Grade 1, 0603", Cap_Case=0603, Manufacturer=TDK, Supplier Part Number 1=445-12548-2-ND, TempCo=X7R, Tolerance_%=20%, Value2=25V, ValueDisplayed=1µF
C31 C32: library part CMP-0006979-5, "CAP, CERM, 0.1 uF, 25 V, +/- 10%, X7R, 0603", Cap_Case=0603, Manufacturer=Kemet, Supplier Part Number 1=399-5345-1-ND, TempCo=X7R, Tolerance_%=10%, Value1=Unknown, Value2=25V, ValueDisplayed=0.1uF
D1 D2: library part CMP-0084855-1, "LED, Red, SMD", Color=Red, Manufacturer="Visual Communications Company, LLC", Power_TotalModule=100mW, Value1=0.1W, Value2=1.7V
D3 D4: library part CMP-0076982-2, "Diode, Switching, 75 V, 0.3 A, SOD-523F", Manufacturer="Fairchild Semiconductor", Value1=0.3A, Value2=V
DS1: library part CMP-0123821-1, "Character Display Module Reflective 14-Segment TN - Twisted Nematic Without Backlight 52.00mm x 22.00mm x 2.80mm", Digikey Part Number=153-1115-ND, Manufacturer=Varitronix, Mouser Part Number=825-VIM878DPRCSLV, Operating Temperature Range=to
FB1 FB3 FB5 FB6: library part CMP-0037616-1, "4.7 kOhms @ 100 MHz 1 Signal Line Ferrite Bead 0805 (2012 Metric) 850mA 400mOhm", Digikey Part Number=490-BLM21HE472SH1LCT-ND, Impedance At Frequency="4700Ω @ 100MHz", Manufacturer=Murata, Mouser Part Number=81-BLM21HE472SH1L, Operating Temperature Range="-55°C to +125°C"
FB2 FB4: library part CMP-0091663-1, "1.8 kOhms @ 100MHz 1 Power, Signal Line Ferrite Bead 0402 (1005 Metric) 210mA 2.1Ohm", Digikey Part Number=732-74269244182CT-ND, Impedance At Frequency="1800Ω @ 100MHz", Manufacturer="Wurth Electronics", Mouser Part Number=710-74269244182, Operating Temperature Range="-55°C to +125°C", Test Frequency=1GHz, Tolerance_%=25%
H1: library part CMP-0004011-1, "Heatsink, DDPAK/TO-263, SMT", Manufacturer=Aavid, Supplier Part Number 1=HS338CT-ND
H2 H3 H4 H5: library part CMP-0079337-1, "5 mm PCB Hole", Manufacturer=Any
J2: library part CMP-0122186-1, "2 Position Header Connector 0.100\" (2.54mm) Through Hole, Right Angle Tin", Current_A=3A, Digikey Part Number=S5438-ND, Manufacturer=Sullins, Operating Temperature Range="-40°C to +105°C", Voltage_V=250V
J3: library part CMP-0078237-1, "Header, 2.54mm, 3x1, Tin, TH", Color=Black, Current_A=4A, Manufacturer=Molex, Supplier Part Number 1=WM50014-03-ND, Voltage_V=500V
J4: library part CMP-0075634-1, "Header(Shrouded), 1.27mm, 5x2, Gold, SMT", Color=Black, Current_A=3.3A, Manufacturer=Samtec, Supplier Part Number 1=SAM8799-ND
J7: library part CMP-0055506-1, "Terminal Block, 2x1, 5mm, Green, TH", Color=Green, Manufacturer="Phoenix Contact", Supplier Part Number 1=277-6405-ND
Logo1: library part CMP-0074838-1, "Texas Instrument Corporate Signature"
logo2: library part CMP-0074835-1, "IEC 61010-1 High Voltage Warning"
Logo2: library part CMP-0074844-1
Logo3: library part CMP-0074847-1, "FCC_disclaimer"
logo4: library part CMP-0074837-2, "IEC 61010-1 Hot Surface Warning", Manufacturer="Texas Instruments"
Logo4: library part CMP-0074769-1
R1 R2 R3 R4: library part CMP-0018810-2, "RES, 2.00 M, 0.1%, 1 W, 1206", Manufacturer="Vishay Draloric", Power_W=1W, Supplier Part Number 1=541-2324-1-ND, TempCo="25 ppm/C", Tolerance_%=0.1%, Value_Code=2M00, ValueDisplayed=2.00M
R5 R10: library part CMP-0022448-2, "RES, 49.9, 1%, 0.1 W, 0603", Manufacturer=Vishay-Dale, Power_W=100mW, Supplier Part Number 1=541-49.9HCT-ND, TempCo="100 ppm/C", Tolerance_%=1%, Value2=0.1W, Value_Code=49R9, ValueDisplayed=49.9
R6 R9: library part CMP-0022448-4, "RES, 49.9, 1%, 0.1 W, AEC-Q200 Grade 0, 0603", Manufacturer=Vishay-Dale, Power_W=100mW, Supplier Part Number 1=541-49.9HCT-ND, TempCo="100 ppm/C", Tolerance_%=1%, Value2=0.1W, Value_Code=49R9, ValueDisplayed=49.9
R7: library part CMP-0122747-1, "8 kOhms ±0.1% 0.1W, 1/10W Chip Resistor 0603 (1608 Metric) Thin Film", Digikey Part Number=13-RT0603BRE078KLCT-ND, Manufacturer=Yageo, Mouser Part Number=603-RT0603BRE078KL, Operating Temperature Range="-55°C to +155°C", Part Number=RT0603BRE078KL, Power_W=100mW, TempCo=50ppm/°C, Tolerance_%=0.1%
R8: library part CMP-0127357-1, "1 mOhms ±1% 6W Chip Resistor 2512 (6332 Metric) Automotive AEC-Q200, Current Sense Metal Element", Digikey Part Number=4506-EBWM2512F1L00S9CT-ND, Manufacturer=RESI, Operating Temperature Range="-55°C to +170°C", Power_W=6W, TempCo=200ppm/°C, Tolerance_%=1%
R11 R12: library part CMP-0026736-1, "RES, 470, 1%, 0.063 W, 0402", Manufacturer="Yageo America", Power_W=63mW, Supplier Part Number 1=311-470LRCT-ND, TempCo="100 ppm/C", Tolerance_%=1%, Value2=0.063W, Value_Code=470R, ValueDisplayed=470
R13: library part CMP-0026935-3, "RES, 47 k, 5%, 0.063 W, AEC-Q200 Grade 0, 0402", Manufacturer=Vishay-Dale, Power_W=63mW, Supplier Part Number 1=541-47KJCT-ND, TempCo="200 ppm/C", Tolerance_%=5%, Value2=0.063W, Value_Code=47k0, ValueDisplayed=47k
R14: library part CMP-0025817-4, "RES, 4.7 k, 5%, 0.1 W, AEC-Q200 Grade 0, 0603", Manufacturer=Vishay-Dale, Power_W=100mW, Supplier Part Number 1=541-4.7KGCT-ND, TempCo="200 ppm/C", Tolerance_%=5%, Value2=0.1W, Value_Code=4k70, ValueDisplayed=4.7k
R17: library part CMP-0097568-1, "47 kOhms ±1% 0.125W, 1/8W Chip Resistor 0402 (1005 Metric) Automotive AEC-Q200 Thick Film", Digikey Part Number=541-RCC040247K0FKEDCT-ND, Manufacturer="Vishay Dale", Mouser Part Number=71-RCC040247K0FKED, Operating Temperature Range="-55°C to +155°C", Part Number=RCC040247K0FKED, Power_W=125mW, TempCo=100ppm/°C, Tolerance_%=1%
R20: library part CMP-0086033-1, "RES, 0.0005, 1%, 6 W, AEC-Q200 Grade 0, 6.35x3.02mm", Manufacturer=Vishay-Dale, Power_W=6W, TempCo="200 ppm/C", Tolerance_%=1%, Value_Code=L5000, ValueDisplayed=0.0005
RS1: library part CMP-0079577-1, "Receptacle, D-SUB-9, 2.74mm, Gold, TH", Color=Black, Current_A=6A, Manufacturer="TE Connectivity", Supplier Part Number 1=A32036-ND, Voltage_V=125V
SW1: library part CMP-0002143-2, "Switch, Tactile, SPST-NO, 0.05A, 12V, SMT", CurrentRating_mA=50A, Manufacturer=E-Switch, Supplier Part Number 1=EG4344CT-ND
T2 T3: library part CMP-0055443-2, "Terminal 90A Lug", Manufacturer=Panduit, Supplier Part Number 1=CB70-14-CY-ND, Voltage_V=600V
U1: library part CMP-0093943-1, "3-Channel, Simultaneously-Sampling, 24-Bit, Reinforced Isolated DeltaSigma ADC With Integrated DC/DC Converter", Manufacturer="Texas Instruments", Max Supply Voltage=5.5V, Min Supply Voltage=3V, Operating Temperature Range="-40°C to +125°C"
U2: library part CMP-0094692-4, "Mixed-Signal Microcontrollers", Frequency_Fixed=80MHz, Manufacturer="Texas Instruments", Max Supply Voltage=3.6V, Min Supply Voltage=1.35V, Operating Temperature Range="-40°C to +125°C"
U3: library part CMP-0073793-1, "150-mA, 30-V, Ultra-Low IQ, Wide Input Low-Dropout Regulator with Reverse Current Protection, DBV0005A (SOT-23-5)", Alternate Manufacturer="Texas Instruments", Alternate PartNumber=TPS70933DBVT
